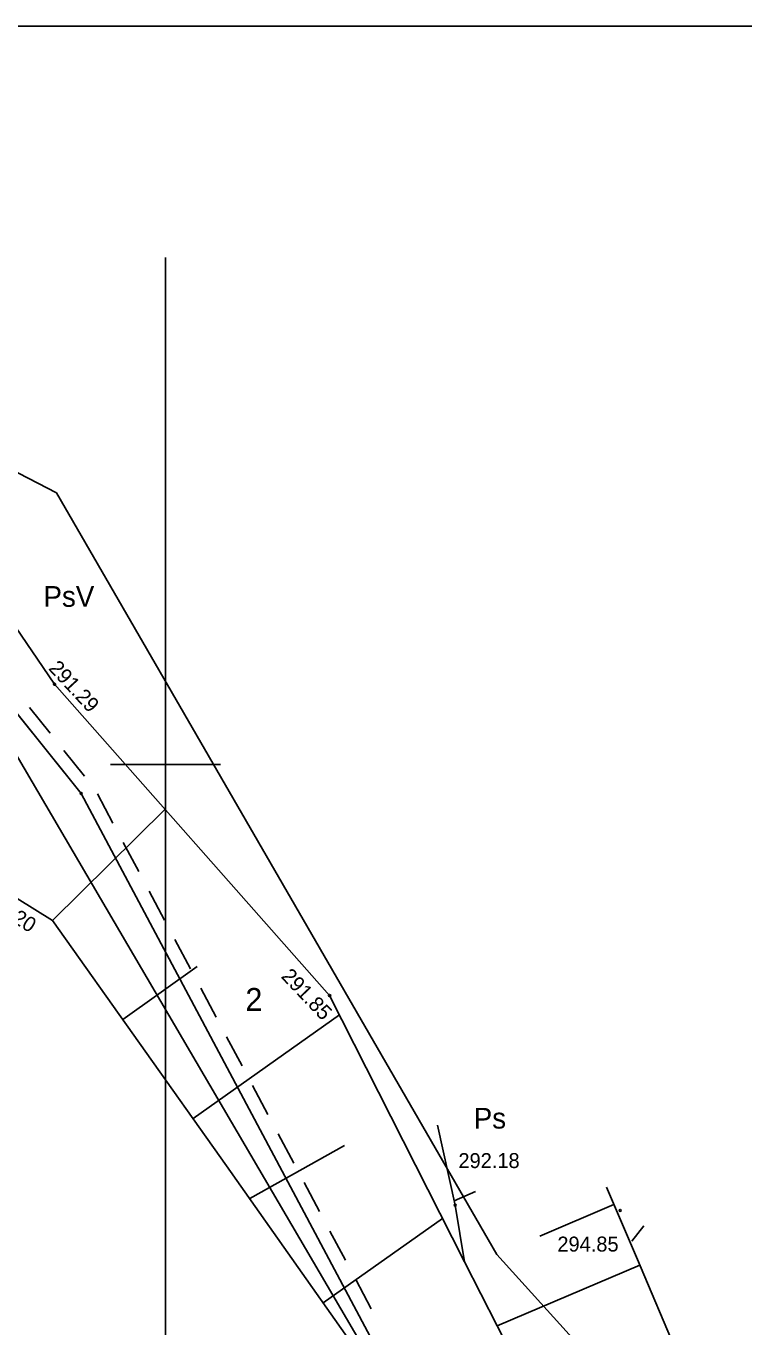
# Model space of a CAD drawing. Extents: x 7477803 to 7478145, y 5500698 to 5500984.
# Drawn here: x 7477993.7 to 7478026.3, y 5500924.5 to 5500983.6 of the extents above; entities that cross this region are included whole.
import ezdxf

# ---------------------------------------------------------------- set-up
doc = ezdxf.new("R2010")
doc.units = 0
for name, color, linetype in [('203-Punkt załamania granicy działki nie stabilizowany', 7, 'Continuous'), ('gr_dzialki', 7, 'Continuous'), ('gr_klasy', 7, 'Continuous'), ('k', 7, 'Continuous'), ('nr_dzialki', 7, 'Continuous'), ('opis_klasy', 7, 'Continuous'), ('opis_uzytek', 7, 'Continuous'), ('pkt_wys', 7, 'Continuous'), ('pob_gr_obrebu', 7, 'Continuous'), ('robocza11', 7, 'Continuous'), ('robocza49', 7, 'Continuous'), ('skarp_wypel', 7, 'Continuous'), ('skarpa_gora', 7, 'Continuous'), ('warst_pogrub', 7, 'Continuous'), ('zakresy', 7, 'Continuous')]:
    doc.layers.add(name, color=color, linetype=linetype)

# ---------------------------------------------------------------- blocks, each defined once
blk = doc.blocks.new('203')
blk.add_circle((0, 0), 0.045)
blk = doc.blocks.new('801_3')
at = {"layer": 'pkt_wys'}
blk.add_circle((0, 0), 0.045, dxfattribs=at)
blk.add_circle((0, 0), 0.045, dxfattribs=at)
blk = doc.blocks.new('801_5')
at = {"layer": 'pkt_wys'}
blk.add_circle((0, 0), 0.05, dxfattribs=at)
blk.add_circle((0, 0), 0.05, dxfattribs=at)

msp = doc.modelspace()

# ---------------------------------------------------------------- linework, layer by layer
at = {"layer": 'gr_dzialki'}
for points in [[(7477986.83, 5500960.33), (7477996.18, 5500948.69)], [(7477996.18, 5500948.69), (7478011.06, 5500920.71)]]:
    msp.add_lwpolyline(points, dxfattribs=at)
at = {"layer": 'gr_klasy'}
for points in [[(7477996.18, 5500948.69), (7477987.47, 5500959.53)], [(7478011.06, 5500920.71), (7477996.18, 5500948.69)]]:
    msp.add_lwpolyline(points, dxfattribs=at)
at = {"layer": 'k'}
msp.add_line((7477991.676, 5500953.076), (7478020.436, 5500903.997), dxfattribs=at)
at = {"layer": 'pkt_wys'}
for points in [[(7477994.915, 5500953.642), (7477994.964, 5500953.65), (7477994.997, 5500953.613)], [(7477994.997, 5500953.613), (7477994.964, 5500953.65), (7477994.915, 5500953.642)], [(7477994.915, 5500953.642), (7477994.964, 5500953.65), (7477994.997, 5500953.613)], [(7477994.997, 5500953.613), (7477994.964, 5500953.65), (7477994.915, 5500953.642)]]:
    msp.add_lwpolyline(points, dxfattribs=at)
for start, end in [(312.22025, 189.91464), (312.22025, 189.91464), (189.91464, 312.22025), (189.91464, 312.22025)]:
    msp.add_arc((7477994.964, 5500953.65), 0.05, start, end, dxfattribs=at)
at = {"layer": 'pob_gr_obrebu'}
for p, q in [((7477993.821, 5500952.59), (7477994.761, 5500951.421)), ((7477995.387, 5500950.641), (7477996.327, 5500949.472)), ((7477996.913, 5500948.665), (7477997.617, 5500947.341)), ((7477998.086, 5500946.458), (7477998.79, 5500945.134)), ((7477999.26, 5500944.251), (7477999.964, 5500942.926)), ((7478000.434, 5500942.043), (7478001.138, 5500940.719)), ((7478001.607, 5500939.836), (7478002.312, 5500938.512)), ((7478002.781, 5500937.629), (7478003.485, 5500936.304)), ((7478003.955, 5500935.421), (7478004.659, 5500934.097)), ((7478005.128, 5500933.214), (7478005.833, 5500931.89)), ((7478006.302, 5500931.007), (7478007.006, 5500929.682)), ((7478007.476, 5500928.799), (7478008.18, 5500927.475)), ((7478008.649, 5500926.592), (7478009.354, 5500925.267))]:
    msp.add_line(p, q, dxfattribs=at)
at = {"layer": 'robocza11'}
msp.add_lwpolyline([(7478014.996, 5500697.565), (7478144.729, 5500697.565), (7478144.729, 5500983.565), (7477803.256, 5500983.565), (7477803.256, 5500697.565), (7478010.821, 5500697.565)], close=True, dxfattribs=at)
at = {"layer": 'robocza49'}
for p, q in [((7478000, 5500750), (7478000, 5500973.047)), ((7477997.5, 5500950), (7478000, 5500950)), ((7478000, 5500950), (7478002.5, 5500950))]:
    msp.add_line(p, q, dxfattribs=at)
at = {"layer": 'skarp_wypel'}
for p, q in [((7477994.866, 5500942.92), (7477999.985, 5500947.965)), ((7477998.061, 5500938.416), (7478001.444, 5500940.816)), ((7478001.257, 5500933.912), (7478007.903, 5500938.628)), ((7478003.83, 5500930.275), (7478008.13, 5500932.693)), ((7478014.095, 5500930.593), (7478013.122, 5500930.179)), ((7478020.376, 5500930.003), (7478017.005, 5500928.57)), ((7478007.165, 5500925.54), (7478012.596, 5500929.365)), ((7478021.55, 5500927.242), (7478015.067, 5500924.486))]:
    msp.add_line(p, q, dxfattribs=at)
at = {"layer": 'skarpa_gora'}
for points in [[(7477994.964, 5500953.65), (7477989.125, 5500962.227), (7477992.08, 5500964.748)], [(7478013.594, 5500927.395), (7478007.459, 5500939.504), (7477994.964, 5500953.65)], [(7478007.879, 5500866.795), (7478009.357, 5500868.166), (7477985.351, 5500883.4), (7477939.898, 5500913.11), (7477944.561, 5500919.785), (7477954.951, 5500928.707), (7477971.014, 5500935.434), (7477981.218, 5500940.405), (7477991.643, 5500944.907), (7477994.866, 5500942.92), (7478002.778, 5500931.769), (7478021.266, 5500905.519), (7478029.289, 5500903.308), (7478032.779, 5500894.332), (7478047.773, 5500881.148)], [(7478012.369, 5500933.612), (7478013.17, 5500929.97), (7478013.594, 5500927.395)], [(7478020.042, 5500930.79), (7478021.395, 5500927.609)], [(7478015.067, 5500924.486), (7478013.594, 5500927.395)], [(7478021.395, 5500927.609), (7478025.254, 5500918.53)], [(7478047.773, 5500881.148), (7478035.389, 5500893.665), (7478029.997, 5500905.289), (7478021.54, 5500911.709), (7478015.067, 5500924.486)]]:
    msp.add_lwpolyline(points, dxfattribs=at)
at = {"layer": 'warst_pogrub'}
msp.add_lwpolyline([(7478021.739, 5500929.039), (7478021.192, 5500928.344)], dxfattribs=at)
at = {"layer": 'zakresy'}
msp.add_lwpolyline([(7477995.059, 5500962.348), (7477983.951, 5500968.084), (7477970.781, 5500968.613), (7477936.09, 5500958.171), (7477930.511, 5500954.336), (7477914.305, 5500958.58), (7477904.32, 5500957.41), (7477897.265, 5500950.868), (7477811.424, 5500829.338), (7477936.003, 5500769.492), (7478008.982, 5500726.585), (7478019.402, 5500721.781), (7478037.95, 5500734.97), (7478039.493, 5500755.094), (7478043.98, 5500765.708), (7478067.545, 5500795.068), (7478092.109, 5500820.25), (7478076.156, 5500837.989), (7478068.105, 5500851.146), (7478061.422, 5500873.298), (7478054.135, 5500876.371), (7478039.669, 5500897.644), (7478026.36, 5500915.23), (7478015.054, 5500927.728)], close=True, dxfattribs=at)

# ---------------------------------------------------------------- block references
at = {"layer": '203-Punkt załamania granicy działki nie stabilizowany'}
msp.add_blockref('203', (7477996.18, 5500948.69), dxfattribs=at)
at = {"layer": 'pkt_wys', "rotation": 0.0626175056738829}
for name, p in [('801_5', (7478007.459, 5500939.504)), ('801_3', (7478013.17, 5500929.97)), ('801_3', (7478020.66, 5500929.739))]:
    msp.add_blockref(name, p, dxfattribs=at)

# ---------------------------------------------------------------- texts
at = {"layer": 'nr_dzialki'}
msp.add_text('2', height=1.04, dxfattribs=at).set_placement((7478003.634, 5500938.804))
at = {"layer": 'opis_klasy'}
msp.add_text('PsV', height=0.94, dxfattribs=at).set_placement((7477994.465, 5500957.17))
at = {"layer": 'opis_uzytek'}
msp.add_text('Ps', height=0.94, dxfattribs=at).set_placement((7478014.01, 5500933.457))
at = {"layer": 'pkt_wys'}
for s, rotation, p in [('291.29', 312.9571, (7477994.658, 5500954.346)), ('297.20', 327.56397, (7477991.502, 5500943.824)), ('291.85', 313.55518, (7478005.221, 5500940.343)), ('292.18', 0.06262, (7478013.313, 5500931.659)), ('294.85', 0.06262, (7478017.808, 5500927.866))]:
    msp.add_text(s, height=0.68, rotation=rotation, dxfattribs=at).set_placement(p)

doc.saveas('drawing.dxf')
